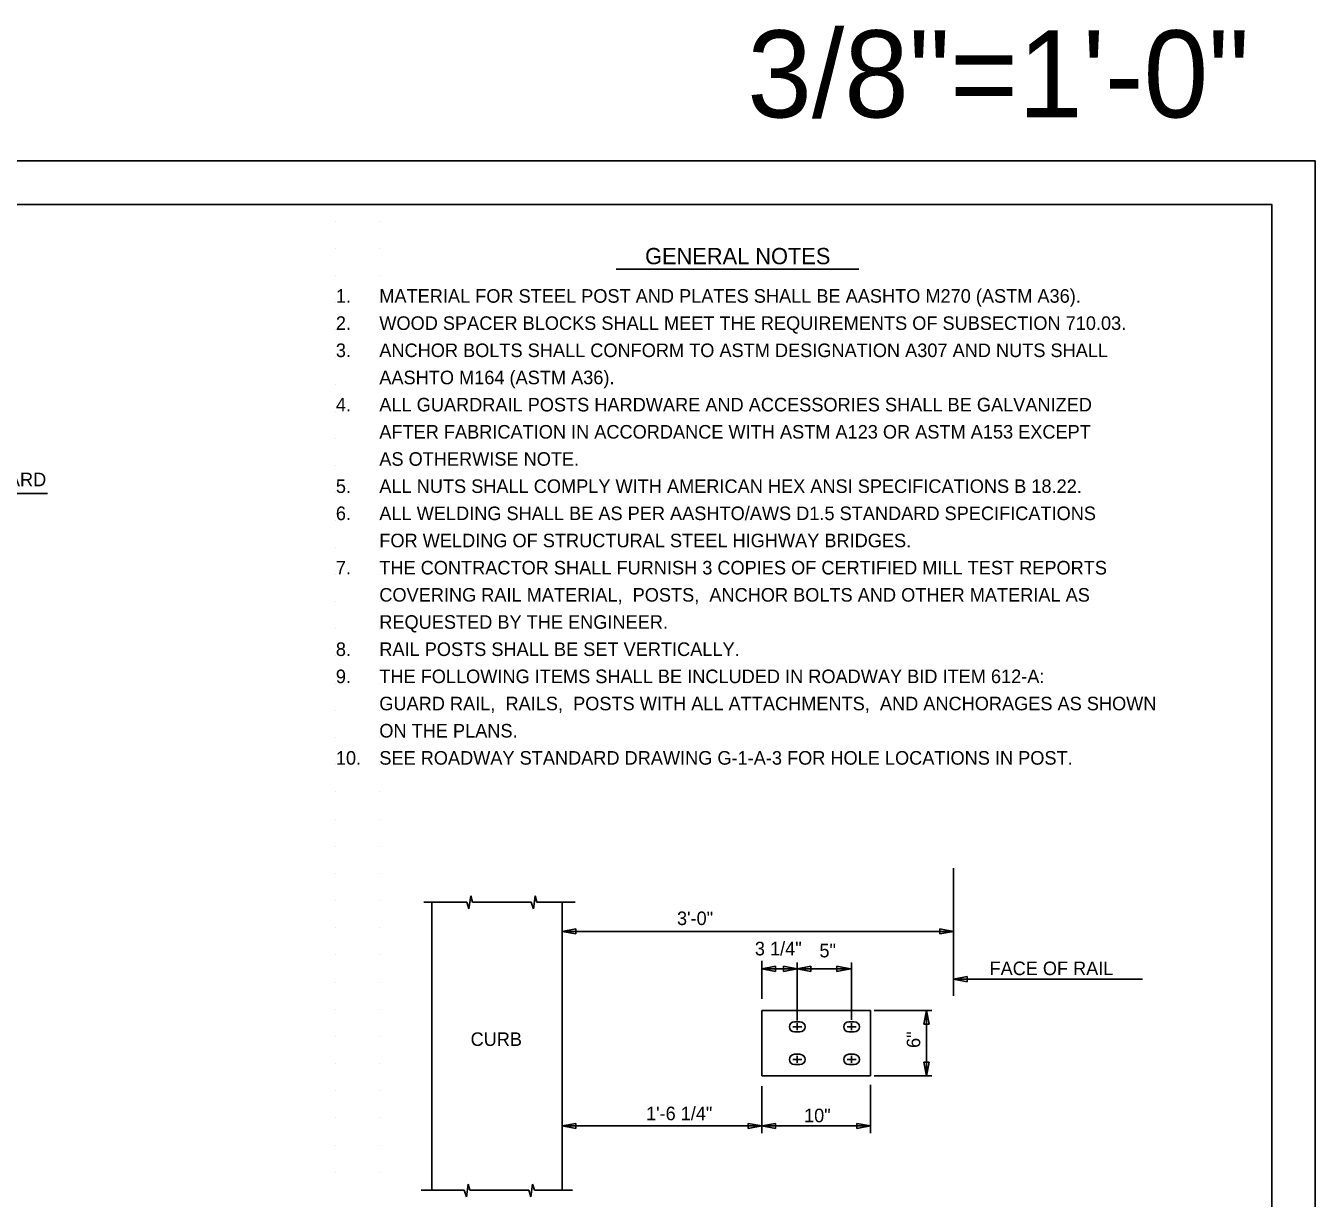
# Model space of a CAD drawing. Extents: x 0 to 90.7, y 0 to 62.8.
# Drawn here: x 51.11 to 90.67, y 26.85 to 62.81 of the extents above; entities that cross this region are included whole.
import ezdxf

# ---------------------------------------------------------------- set-up
doc = ezdxf.new("R2010")
doc.units = 0
for name, color, linetype in [('BORDER_ANNO_Cutsheet', 7, 'Continuous'), ('BRDG_ANNO_Anno-Sheet', 7, 'Continuous'), ('BRDG_ANNO_General-Notes', 7, 'Continuous'), ('BRDG_BASE_Active-Point', 7, 'Continuous'), ('BRDG_BASE_Dtlctrln', 7, 'Continuous'), ('BRDG_BASE_Obj-Line', 7, 'Continuous')]:
    doc.layers.add(name, color=color, linetype=linetype)

msp = doc.modelspace()

# ---------------------------------------------------------------- linework, layer by layer
at = {"layer": 'BORDER_ANNO_Cutsheet'}
msp.add_lwpolyline([(0, 58.667), (90.667, 58.667), (90.667, 0), (0, 0)], close=True, dxfattribs=at)
at = {"layer": 'BRDG_ANNO_Anno-Sheet'}
msp.add_lwpolyline([(4, 57.333), (89.333, 57.333), (89.333, 1.333), (4, 1.333)], close=True, dxfattribs=at)
at = {"layer": 'BRDG_ANNO_General-Notes'}
for p, q in [((69.224, 55.341), (76.663, 55.341)), ((51.779, 48.466), (43.962, 48.466)), ((67.57, 35.035), (67.99, 35.114)), ((67.57, 35.035), (79.57, 35.035)), ((67.99, 34.956), (67.57, 35.035)), ((67.99, 35.114), (67.99, 34.956)), ((79.15, 34.956), (79.15, 35.114)), ((79.15, 35.114), (79.57, 35.035)), ((79.57, 35.035), (79.15, 34.956)), ((73.695, 32.969), (73.695, 34.128)), ((73.695, 33.887), (74.115, 33.966)), ((74.778, 33.887), (73.695, 33.887)), ((74.115, 33.808), (73.695, 33.887)), ((74.115, 33.966), (74.115, 33.808)), ((74.358, 33.808), (74.358, 33.966)), ((74.358, 33.966), (74.778, 33.887)), ((74.778, 33.887), (74.358, 33.808)), ((74.778, 33.887), (75.198, 33.966)), ((74.778, 33.887), (76.416, 33.887)), ((75.198, 33.808), (74.778, 33.887)), ((75.198, 33.966), (75.198, 33.808)), ((75.996, 33.808), (75.996, 33.966)), ((75.996, 33.966), (76.416, 33.887)), ((76.416, 33.887), (75.996, 33.808)), ((79.57, 33.568), (79.99, 33.647)), ((79.99, 33.647), (79.99, 33.489)), ((79.57, 33.568), (85.364, 33.568)), ((79.99, 33.489), (79.57, 33.568)), ((77.133, 32.609), (78.268, 32.609)), ((77.292, 32.609), (78.903, 32.609)), ((78.665, 32.189), (78.744, 32.609)), ((78.744, 30.609), (78.744, 32.609)), ((78.744, 32.609), (78.822, 32.189)), ((74.778, 32.109), (74.642, 32.109)), ((74.778, 32.109), (74.778, 32.217)), ((74.778, 32.109), (74.915, 32.109)), ((74.778, 32.109), (74.778, 32.001)), ((76.445, 32.109), (76.309, 32.109)), ((76.445, 32.109), (76.445, 32.217)), ((76.445, 32.109), (76.582, 32.109)), ((76.445, 32.109), (76.445, 32.001)), ((78.822, 32.189), (78.665, 32.189)), ((74.778, 31.109), (74.642, 31.109)), ((74.778, 31.109), (74.778, 31.217)), ((74.778, 31.109), (74.915, 31.109)), ((74.778, 31.109), (74.778, 31.001)), ((76.445, 31.109), (76.309, 31.109)), ((76.445, 31.109), (76.445, 31.217)), ((76.445, 31.109), (76.582, 31.109)), ((76.445, 31.109), (76.445, 31.001)), ((78.665, 31.029), (78.822, 31.029)), ((78.744, 30.609), (78.665, 31.029)), ((78.822, 31.029), (78.744, 30.609)), ((77.133, 30.609), (78.268, 30.609)), ((77.331, 30.609), (78.903, 30.609)), ((73.695, 30.286), (73.695, 28.842)), ((77.029, 30.325), (77.029, 28.842)), ((67.57, 29.069), (67.99, 29.147)), ((73.695, 29.069), (67.57, 29.069)), ((67.99, 28.99), (67.57, 29.069)), ((67.99, 29.147), (67.99, 28.99)), ((73.275, 28.99), (73.275, 29.147)), ((73.275, 29.147), (73.695, 29.069)), ((73.695, 29.069), (73.275, 28.99)), ((73.695, 29.069), (74.115, 29.147)), ((73.695, 29.069), (77.029, 29.069)), ((74.115, 28.99), (73.695, 29.069)), ((74.115, 29.147), (74.115, 28.99)), ((76.609, 28.99), (76.609, 29.147)), ((76.609, 29.147), (77.029, 29.069)), ((77.029, 29.069), (76.609, 28.99))]:
    msp.add_line(p, q, dxfattribs=at)
at = {"layer": 'BRDG_BASE_Active-Point'}
for p, q in [((60.625, 56.815), (60.625, 56.815)), ((61.958, 56.815), (61.958, 56.815)), ((60.625, 55.981), (60.625, 55.981)), ((61.958, 55.981), (61.958, 55.981)), ((60.625, 55.148), (60.625, 55.148)), ((61.958, 55.148), (61.958, 55.148)), ((60.625, 54.315), (60.625, 54.315)), ((61.958, 54.315), (61.958, 54.315)), ((60.625, 53.481), (60.625, 53.481)), ((61.958, 53.481), (61.958, 53.481)), ((60.625, 52.648), (60.625, 52.648)), ((61.958, 52.648), (61.958, 52.648)), ((60.625, 51.815), (60.625, 51.815)), ((61.958, 51.815), (61.958, 51.815)), ((60.625, 50.981), (60.625, 50.981)), ((61.958, 50.981), (61.958, 50.981)), ((60.625, 50.148), (60.625, 50.148)), ((61.958, 50.148), (61.958, 50.148)), ((60.625, 49.315), (60.625, 49.315)), ((61.958, 49.315), (61.958, 49.315)), ((60.625, 48.481), (60.625, 48.481)), ((61.958, 48.481), (61.958, 48.481)), ((60.625, 47.648), (60.625, 47.648)), ((61.958, 47.648), (61.958, 47.648)), ((60.625, 46.815), (60.625, 46.815)), ((61.958, 46.815), (61.958, 46.815)), ((60.625, 45.981), (60.625, 45.981)), ((61.958, 45.981), (61.958, 45.981)), ((60.625, 45.148), (60.625, 45.148)), ((61.958, 45.148), (61.958, 45.148)), ((60.625, 44.315), (60.625, 44.315)), ((61.958, 44.315), (61.958, 44.315)), ((60.625, 43.481), (60.625, 43.481)), ((61.958, 43.481), (61.958, 43.481)), ((60.625, 42.648), (60.625, 42.648)), ((61.958, 42.648), (61.958, 42.648)), ((60.625, 41.815), (60.625, 41.815)), ((61.958, 41.815), (61.958, 41.815)), ((60.625, 40.981), (60.625, 40.981)), ((61.958, 40.981), (61.958, 40.981)), ((60.625, 40.148), (60.625, 40.148)), ((61.958, 40.148), (61.958, 40.148)), ((60.625, 39.315), (60.625, 39.315)), ((61.958, 39.315), (61.958, 39.315)), ((60.625, 38.481), (60.625, 38.481)), ((61.958, 38.481), (61.958, 38.481)), ((60.625, 37.648), (60.625, 37.648)), ((61.958, 37.648), (61.958, 37.648)), ((60.625, 36.815), (60.625, 36.815)), ((61.958, 36.815), (61.958, 36.815)), ((60.625, 35.981), (60.625, 35.981)), ((61.958, 35.981), (61.958, 35.981)), ((60.625, 35.148), (60.625, 35.148)), ((61.958, 35.148), (61.958, 35.148)), ((60.625, 34.315), (60.625, 34.315)), ((61.958, 34.315), (61.958, 34.315)), ((60.625, 33.481), (60.625, 33.481)), ((61.958, 33.481), (61.958, 33.481)), ((60.625, 32.648), (60.625, 32.648)), ((61.958, 32.648), (61.958, 32.648)), ((60.625, 31.815), (60.625, 31.815)), ((61.958, 31.815), (61.958, 31.815)), ((60.625, 30.981), (60.625, 30.981)), ((61.958, 30.981), (61.958, 30.981)), ((60.625, 30.148), (60.625, 30.148)), ((61.958, 30.148), (61.958, 30.148)), ((60.625, 29.315), (60.625, 29.315)), ((61.958, 29.315), (61.958, 29.315)), ((60.625, 28.481), (60.625, 28.481)), ((61.958, 28.481), (61.958, 28.481)), ((60.625, 27.648), (60.625, 27.648)), ((61.958, 27.648), (61.958, 27.648))]:
    msp.add_line(p, q, dxfattribs=at)
at = {"layer": 'BRDG_BASE_Dtlctrln'}
for p, q in [((74.778, 32.303), (74.778, 34.077)), ((76.445, 32.324), (76.445, 34.077))]:
    msp.add_line(p, q, dxfattribs=at)
at = {"layer": 'BRDG_BASE_Obj-Line'}
for p, q in [((79.57, 33.056), (79.57, 36.972)), ((64.709, 35.726), (64.761, 36.121)), ((64.761, 36.121), (64.815, 35.934)), ((66.687, 35.726), (66.74, 36.121)), ((66.74, 36.121), (66.793, 35.934)), ((64.641, 35.934), (63.323, 35.934)), ((63.57, 27.129), (63.57, 35.95)), ((64.641, 35.934), (64.709, 35.726)), ((66.619, 35.934), (64.815, 35.934)), ((66.619, 35.934), (66.687, 35.726)), ((67.963, 35.934), (66.793, 35.934)), ((67.57, 27.129), (67.57, 35.95)), ((77.029, 32.609), (73.695, 32.609)), ((73.695, 32.609), (73.695, 30.609)), ((77.029, 30.609), (77.029, 32.609)), ((74.695, 32.266), (74.862, 32.266)), ((74.778, 32.109), (74.778, 32.109)), ((76.362, 32.266), (76.529, 32.266)), ((76.445, 32.109), (76.445, 32.109)), ((74.695, 31.953), (74.862, 31.953)), ((76.362, 31.953), (76.529, 31.953)), ((74.695, 31.265), (74.862, 31.265)), ((76.362, 31.265), (76.529, 31.265)), ((74.695, 30.953), (74.862, 30.953)), ((74.778, 31.109), (74.778, 31.109)), ((76.362, 30.953), (76.529, 30.953)), ((76.445, 31.109), (76.445, 31.109)), ((73.695, 30.609), (77.029, 30.609)), ((64.564, 27.098), (63.246, 27.098)), ((64.564, 27.098), (64.632, 26.89)), ((64.632, 26.89), (64.684, 27.285)), ((64.684, 27.285), (64.738, 27.098)), ((66.542, 27.098), (64.738, 27.098)), ((66.542, 27.098), (66.61, 26.89)), ((66.61, 26.89), (66.662, 27.285)), ((66.662, 27.285), (66.716, 27.098)), ((67.886, 27.098), (66.716, 27.098))]:
    msp.add_line(p, q, dxfattribs=at)
for centre, start, end in [((74.695, 32.109), 90, 270), ((74.862, 32.109), 270, 90), ((76.362, 32.109), 90, 270), ((76.529, 32.109), 270, 90), ((74.695, 31.109), 90, 270), ((74.862, 31.109), 270, 90), ((76.362, 31.109), 90, 270), ((76.529, 31.109), 270, 90)]:
    msp.add_arc(centre, 0.156, start, end, dxfattribs=at)

# ---------------------------------------------------------------- texts
at = {"layer": 'BRDG_ANNO_Anno-Sheet'}
msp.add_text('3/8"=1\'-0"', height=2.6667, dxfattribs=at).set_placement((73.245, 60))
at = {"layer": 'BRDG_ANNO_General-Notes'}
for s, height, p in [('GENERAL NOTES', 0.5, (70.11, 55.496)), ('1.', 0.4167, (60.625, 54.315)), ('MATERIAL FOR STEEL POST AND PLATES SHALL BE AASHTO M270 (ASTM A36).', 0.41667, (61.958, 54.315)), ('2.', 0.4167, (60.625, 53.481)), ('WOOD SPACER BLOCKS SHALL MEET THE REQUIREMENTS OF SUBSECTION 710.03.', 0.41667, (61.958, 53.481)), ('3.', 0.4167, (60.625, 52.648)), ('ANCHOR BOLTS SHALL CONFORM TO ASTM DESIGNATION A307 AND NUTS SHALL', 0.41667, (61.958, 52.648)), ('AASHTO M164 (ASTM A36).', 0.41667, (61.958, 51.815)), ('4.', 0.4167, (60.625, 50.981)), ('ALL GUARDRAIL POSTS HARDWARE AND ACCESSORIES SHALL BE GALVANIZED', 0.41667, (61.958, 50.981)), ('AFTER FABRICATION IN ACCORDANCE WITH ASTM A123 OR ASTM A153 EXCEPT', 0.41667, (61.958, 50.148)), ('AS OTHERWISE NOTE.', 0.41667, (61.958, 49.315)), ('SEE ROADWAY STANDARD', 0.41667, (44.372, 48.687)), ('5.', 0.4167, (60.625, 48.481)), ('ALL NUTS SHALL COMPLY WITH AMERICAN HEX ANSI SPECIFICATIONS B 18.22.', 0.41667, (61.958, 48.481)), ('6.', 0.4167, (60.625, 47.648)), ('ALL WELDING SHALL BE AS PER AASHTO/AWS D1.5 STANDARD SPECIFICATIONS', 0.41667, (61.958, 47.648)), ('FOR WELDING OF STRUCTURAL STEEL HIGHWAY BRIDGES.', 0.41667, (61.958, 46.815)), ('7.', 0.4167, (60.625, 45.981)), ('THE CONTRACTOR SHALL FURNISH 3 COPIES OF CERTIFIED MILL TEST REPORTS', 0.41667, (61.958, 45.981)), ('COVERING RAIL MATERIAL,  POSTS,  ANCHOR BOLTS AND OTHER MATERIAL AS', 0.41667, (61.958, 45.148)), ('REQUESTED BY THE ENGINEER.', 0.41667, (61.958, 44.315)), ('8.', 0.4167, (60.625, 43.481)), ('RAIL POSTS SHALL BE SET VERTICALLY.', 0.41667, (61.958, 43.481)), ('9.', 0.4167, (60.625, 42.648)), ('THE FOLLOWING ITEMS SHALL BE INCLUDED IN ROADWAY BID ITEM 612-A:', 0.41667, (61.958, 42.648)), ('GUARD RAIL,  RAILS,  POSTS WITH ALL ATTACHMENTS,  AND ANCHORAGES AS SHOWN', 0.41667, (61.958, 41.815)), ('ON THE PLANS.', 0.41667, (61.958, 40.981)), ('10.', 0.4167, (60.625, 40.148)), ('SEE ROADWAY STANDARD DRAWING G-1-A-3 FOR HOLE LOCATIONS IN POST.', 0.41667, (61.958, 40.148)), ('3\'-0"', 0.4156, (71.09, 35.229)), ('3 1/4"', 0.4167, (73.478, 34.299)), ('5"', 0.4167, (75.458, 34.238)), ('FACE OF RAIL', 0.41562, (80.677, 33.694)), ('CURB', 0.4156, (64.759, 31.522)), ('1\'-6 1/4"', 0.4156, (70.14, 29.244)), ('10"', 0.4167, (74.986, 29.181))]:
    msp.add_text(s, height=height, dxfattribs=at).set_placement(p)
msp.add_text('6"', height=0.4156, rotation=90, dxfattribs=at).set_placement((78.551, 31.46))

doc.saveas('drawing.dxf')
